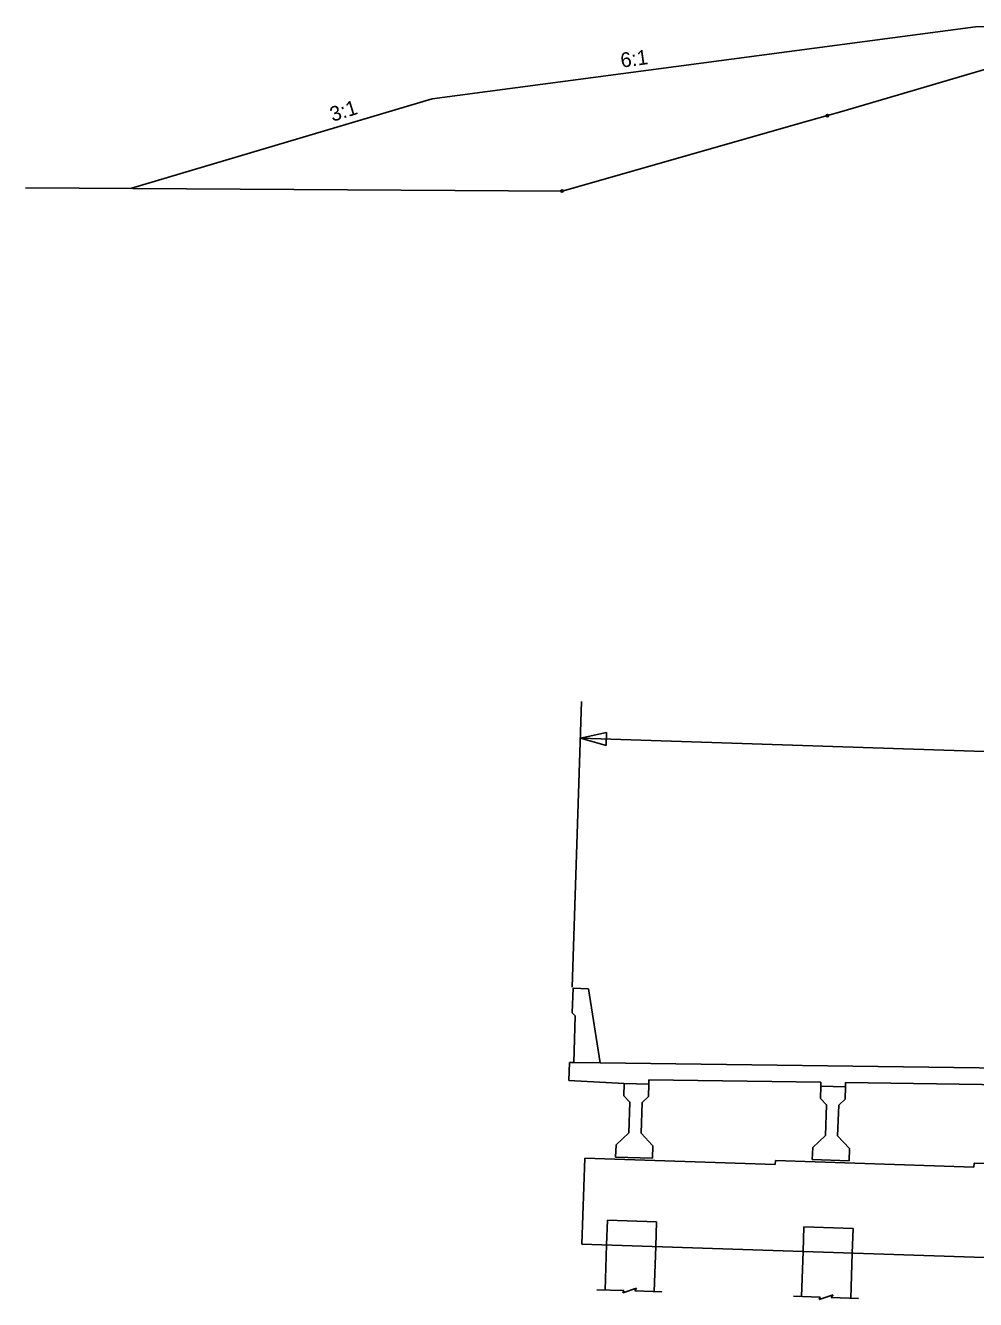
# Model space of a CAD drawing. Extents: x 977258 to 978774, y 1525947 to 1526932.
# Drawn here: x 977258 to 977645, y 1526219 to 1526738 of the extents above; entities that cross this region are included whole.
import ezdxf

# ---------------------------------------------------------------- set-up
doc = ezdxf.new("R2010")
doc.units = 0
for name, color, linetype in [('B_border', 7, 'Continuous'), ('B_Preliminary', 7, 'Continuous'), ('B_Print_Date_Text', 7, 'Continuous'), ('BDR_Plan Profile Grid 1', 7, 'Continuous'), ('BDR_Plan Profile Grid 5', 7, 'Continuous'), ('BDR_Plan Profile Grid 6', 7, 'Continuous'), ('R_Border', 7, 'Continuous'), ('STAMP_PP', 7, 'Continuous')]:
    doc.layers.add(name, color=color, linetype=linetype)

msp = doc.modelspace()

# ---------------------------------------------------------------- linework, layer by layer
at = {"layer": 'B_border'}
for centre in [(977584.62, 1526700.89), (977476.71, 1526670.18)]:
    msp.add_circle(centre, 0.5, dxfattribs=at)
at = {"layer": 'B_Preliminary'}
msp.add_lwpolyline([(977258.38, 1526671.55), (977476.71, 1526670.18), (977576.91, 1526698.71), (977584.62, 1526700.89), (977590.5, 1526702.57), (977665.58, 1526724.58)], dxfattribs=at)
at = {"layer": 'B_Print_Date_Text'}
for p, q in [((977644.9, 1526736.99), (977423.8, 1526707.68)), ((977644.9, 1526736.99), (977724.96, 1526737.52)), ((977423.8, 1526707.68), (977301.14, 1526671.28))]:
    msp.add_line(p, q, dxfattribs=at)
at = {"layer": 'BDR_Plan Profile Grid 1'}
for p, q in [((977501.78, 1526223.07), (977490.84, 1526223.43)), ((977506.97, 1526224.01), (977501.36, 1526222.12)), ((977501.36, 1526222.12), (977501.78, 1526223.07)), ((977506.27, 1526222.92), (977506.97, 1526224.01)), ((977517.33, 1526222.55), (977506.27, 1526222.92)), ((977581.73, 1526220.4), (977570.8, 1526220.76)), ((977586.93, 1526221.35), (977581.32, 1526219.45)), ((977586.22, 1526220.25), (977586.93, 1526221.35)), ((977581.32, 1526219.45), (977581.73, 1526220.4)), ((977597.29, 1526219.88), (977586.22, 1526220.25))]:
    msp.add_line(p, q, dxfattribs=at)
at = {"layer": 'BDR_Plan Profile Grid 5'}
for p, q in [((977481.17, 1526346.04), (977480.84, 1526336.05)), ((977481.17, 1526346.04), (977487.42, 1526345.83)), ((977487.42, 1526345.83), (977492.25, 1526315.66)), ((977480.84, 1526336.05), (977482.05, 1526334.76)), ((977481.41, 1526315.8), (977482.05, 1526334.76)), ((977479.75, 1526315.82), (977479.5, 1526308.54)), ((977481.41, 1526315.8), (977479.75, 1526315.82)), ((977867.29, 1526310.65), (977492.25, 1526315.66)), ((977511.97, 1526306.96), (977512.03, 1526308.73)), ((977582.03, 1526307.79), (977512.03, 1526308.73)), ((977479.5, 1526308.54), (977501.97, 1526307.29)), ((977501.97, 1526307.29), (977501.81, 1526302.3)), ((977501.97, 1526307.29), (977501.81, 1526302.3)), ((977501.97, 1526307.29), (977511.97, 1526306.96)), ((977501.97, 1526307.29), (977511.97, 1526306.96)), ((977511.97, 1526306.96), (977511.8, 1526301.96)), ((977511.97, 1526306.96), (977511.8, 1526301.96)), ((977511.97, 1526306.96), (977511.8, 1526301.96)), ((977511.97, 1526306.96), (977511.8, 1526301.96)), ((977581.98, 1526306.23), (977581.81, 1526301.23)), ((977581.98, 1526306.23), (977581.81, 1526301.23)), ((977581.98, 1526306.23), (977582.03, 1526307.79)), ((977581.98, 1526306.23), (977591.98, 1526305.89)), ((977581.98, 1526306.23), (977591.98, 1526305.89)), ((977591.98, 1526305.89), (977591.81, 1526300.9)), ((977591.98, 1526305.89), (977591.81, 1526300.9)), ((977591.98, 1526305.89), (977591.81, 1526300.9)), ((977591.98, 1526305.89), (977591.81, 1526300.9)), ((977591.98, 1526305.89), (977592.03, 1526307.66)), ((977662.04, 1526306.73), (977592.03, 1526307.66)), ((977501.81, 1526302.3), (977504.22, 1526299.72)), ((977501.81, 1526302.3), (977504.22, 1526299.72)), ((977504.22, 1526299.72), (977503.8, 1526287.22)), ((977504.22, 1526299.72), (977503.8, 1526287.22)), ((977509.22, 1526299.55), (977508.8, 1526287.06)), ((977509.22, 1526299.55), (977508.8, 1526287.06)), ((977511.8, 1526301.96), (977509.22, 1526299.55)), ((977511.8, 1526301.96), (977509.22, 1526299.55)), ((977581.81, 1526301.23), (977584.23, 1526298.65)), ((977581.81, 1526301.23), (977584.23, 1526298.65)), ((977584.23, 1526298.65), (977583.81, 1526286.16)), ((977584.23, 1526298.65), (977583.81, 1526286.16)), ((977589.23, 1526298.48), (977588.81, 1526285.99)), ((977589.23, 1526298.48), (977588.81, 1526285.99)), ((977591.81, 1526300.9), (977589.23, 1526298.48)), ((977591.81, 1526300.9), (977589.23, 1526298.48)), ((977498.64, 1526282.39), (977503.8, 1526287.22)), ((977498.64, 1526282.39), (977503.8, 1526287.22)), ((977513.63, 1526281.89), (977508.8, 1526287.06)), ((977513.63, 1526281.89), (977508.8, 1526287.06)), ((977578.65, 1526281.32), (977583.81, 1526286.16)), ((977578.65, 1526281.32), (977583.81, 1526286.16)), ((977593.64, 1526280.82), (977588.81, 1526285.99)), ((977593.64, 1526280.82), (977588.81, 1526285.99)), ((977498.64, 1526282.39), (977498.47, 1526277.39)), ((977498.64, 1526282.39), (977498.47, 1526277.39)), ((977513.63, 1526281.89), (977513.47, 1526276.89)), ((977513.63, 1526281.89), (977513.47, 1526276.89)), ((977578.65, 1526281.32), (977578.48, 1526276.33)), ((977578.65, 1526281.32), (977578.48, 1526276.33)), ((977593.64, 1526280.82), (977593.47, 1526275.83)), ((977593.64, 1526280.82), (977593.47, 1526275.83)), ((977485.95, 1526276.98), (977484.79, 1526242)), ((977485.95, 1526276.98), (977563.41, 1526274.4)), ((977498.47, 1526277.39), (977513.47, 1526276.89)), ((977498.47, 1526277.39), (977513.47, 1526276.89)), ((977563.47, 1526275.99), (977563.41, 1526274.4)), ((977563.47, 1526275.99), (977644.25, 1526273.3)), ((977578.48, 1526276.33), (977593.47, 1526275.83)), ((977578.48, 1526276.33), (977593.47, 1526275.83)), ((977644.31, 1526274.9), (977644.25, 1526273.3)), ((977644.31, 1526274.9), (977725.1, 1526272.21)), ((977884.56, 1526228.67), (977484.79, 1526242)), ((977494.78, 1526241.66), (977494.17, 1526223.32)), ((977514.77, 1526241), (977514.16, 1526222.65)), ((977574.74, 1526239), (977574.13, 1526220.65)), ((977594.73, 1526238.33), (977594.11, 1526219.99))]:
    msp.add_line(p, q, dxfattribs=at)
at = {"layer": 'BDR_Plan Profile Grid 6'}
for p, q in [((977492.25, 1526315.66), (977481.41, 1526315.8)), ((977494.78, 1526241.66), (977495.11, 1526251.66)), ((977495.11, 1526251.66), (977515.1, 1526250.99)), ((977514.77, 1526241), (977515.1, 1526250.99)), ((977574.74, 1526239), (977575.07, 1526248.99)), ((977575.07, 1526248.99), (977595.06, 1526248.33)), ((977594.73, 1526238.33), (977595.06, 1526248.33))]:
    msp.add_line(p, q, dxfattribs=at)
at = {"layer": 'STAMP_PP'}
for p, q in [((977480.77, 1526346.43), (977484.64, 1526462.57)), ((977890.08, 1526434.2), (977484.14, 1526447.74))]:
    msp.add_line(p, q, dxfattribs=at)
msp.add_lwpolyline([(977494.79, 1526450.02), (977484.14, 1526447.74), (977494.61, 1526444.74)], close=True, dxfattribs=at)

# ---------------------------------------------------------------- texts
at = {"layer": 'R_Border'}
for s, rotation, p in [('6:1', 7.7588, (977500.88, 1526720.35)), ('3:1', 17.4294, (977383.33, 1526698.32))]:
    msp.add_text(s, height=6, rotation=rotation, dxfattribs=at).set_placement(p)

doc.saveas('drawing.dxf')
